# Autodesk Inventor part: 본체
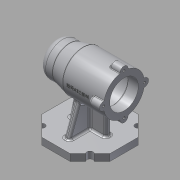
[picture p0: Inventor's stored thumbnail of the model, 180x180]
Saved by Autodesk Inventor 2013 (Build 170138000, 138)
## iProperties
Created: 2021-01
Part Number: 본체
Material: 알루미늄 6061
Document SubType Name: Modeling
Designer: Administrator
Density: 2.71 g/cm^3
Mass: 632.153 g
Surface Area: 615.426 cm^2
Volume: 233.267 cm^3
Author: Administrator
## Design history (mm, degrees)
sketch "스케치1"
  geometry: L1 (0, 0)-(100, 0); L2 (100, 30)-(40, 30); L3 (40, 30)-(20, 25); L4 (20, 25)-(0, 25); L5 (0, 25)-(0, 0); L6 (100, 30)-(100, 21); L7 (100, 21)-(85, 21); L8 (85, 21)-(85, 24); L9 (85, 24)-(43, 24); L10 (43, 24)-(43, 21); L11 (43, 21)-(31, 21); L12 (31, 21)-(31, 17.5); L13 (31, 17.5)-(13, 17.5); L14 (13, 17.5)-(13, 16); L15 (13, 16)-(9, 16); L16 (9, 16)-(9, 10.5); L17 (9, 10.5)-(6, 10.5); L18 (6, 10.5)-(6, 0); 1 further point
  constraints: 36 end point, 12 parallel, 3 perpendicular, 1 coincident, 1 collinear, 1 horizontal, 1 point on line, 1 vertical alignment
  dimensions: "d0" = 100 distance of L1.start L1.end; "d2" = 60 diameter of L2 L1; "d3" = 50 diameter of L4 L1; "d4" = 40 distance from line of L2.end L5; "d5" = 20 distance of L4.end L3.end; "d6" = 42 diameter of L7 L1; "d7" = 48 diameter of L9 L1; "d8" = 42 diameter of L11 L1; "d9" = 35 diameter of L13 L1; "d10" = 32 diameter of L15 L1; "d11" = 21 diameter of L17 L1; "d12" = 15 distance of L6.end L7.end; "d13" = 42 distance of L8.end L9.end; "d14" = 12 distance of L10.end L11.end; "d15" = 18 distance of L12.end L13.end; "d16" = 4 distance of L14.end L15.end; "d17" = 3 distance of L16.end L17.end
revolve "회전1" sketch "스케치1" stored, may be unused: angle "d18" = 90 deg
node "작업 평면1"
sketch "스케치2"
  geometry: L1 (100, -30)-(100, 30) reference; L2 (100, 20.711)-(100, -20.711); L3 (70.711, -50)-(29.289, -50); L4 (0, -20.711)-(0, 20.711); L5 (29.289, 50)-(70.711, 50); L6 (50, 50)-(50, -50); L7 (0, 0)-(100, 0); L8 (70.711, -50)-(100, -20.711); L9 (29.289, -50)-(0, -20.711); L10 (0, 20.711)-(29.289, 50); L11 (70.711, 50)-(100, 20.711); C1 r 50 at (50, 0)
  constraints: 20 end point, 5 perpendicular, 4 midpoint, 4 tangent, 2 point on line, 1 centre point, 1 parallel
  dimensions: "d20" = 50 distance between parallel lines of L6 L2; "d22" = 50 distance between parallel lines of L4 L6; "d24" = 50 distance between parallel lines of L5 L7; "d25" = 50 distance between parallel lines of L3 L7; "d26" = 100 diameter of C1
extrude "돌출1" join sketch "스케치2" distance "d27" = 10; taper "d28" = 0 deg
node "작업 평면2"
node "작업 평면3"
sketch "스케치5"
  geometry: L1 (0, 0)-(-30, 0); A1 r 6 centre (-30, 0) between (-29.4, 5.97) and (-29.4, -5.97); A2 r 30 centre (0, 0) between (-30, 0) and (-29.4, 5.97) reference
  constraints: 5 point on circle, 2 end point, 1 centre point, 1 coincident, 1 horizontal
  dimensions: "d49" = 12 diameter of A1
extrude "돌출3" join sketch "스케치5" distance "d51" = 16; taper "d52" = 0 deg
sketch "스케치6"
  geometry: L1 (29.289, -50)-(70.711, -50) reference; L2 (0, -20.711)-(29.289, -50) reference; L3 (0, 20.711)-(0, -20.711) reference; L4 (29.289, 50)-(0, 20.711) reference; L5 (70.711, 50)-(29.289, 50) reference; L6 (100, 20.711)-(70.711, 50) reference; L7 (100, -20.711)-(100, 20.711) reference; L8 (70.711, -50)-(100, -20.711) reference; L9 (0, -20.711)-(29.289, -50) reference; L10 (70.711, -50)-(100, -20.711) reference; L11 (100, 20.711)-(70.711, 50) reference; L12 (29.289, 50)-(0, 20.711) reference; C1 r 4.5 at (14.645, -35.355); C2 r 4.5 at (85.355, -35.355); C3 r 4.5 at (85.355, 35.355); C4 r 4.5 at (14.645, 35.355); 1 further point
  constraints: 4 centre point, 4 midpoint, 3 equal radius
  dimensions: "d56" = 9 diameter of C4
extrude "돌출4" cut sketch "스케치6" stored distance "d58" = 16; taper "d59" = 0 deg
sketch "스케치7"
  geometry: C1 r 21 at (30, 0) reference; A1 r 30 centre (30, 0) between (0.6, -5.97) and (24.03, -29.4) reference; A2 r 6 centre (30, -30) between (24.03, -29.4) and (35.97, -29.4) reference; A3 r 30 centre (30, 0) between (35.97, -29.4) and (59.4, -5.97) reference; A4 r 6 centre (60, 0) between (59.4, -5.97) and (59.4, 5.97) reference; A5 r 30 centre (30, 0) between (59.4, 5.97) and (35.97, 29.4) reference; A6 r 6 centre (30, 30) between (35.97, 29.4) and (24.03, 29.4) reference; A7 r 30 centre (30, 0) between (24.03, 29.4) and (0.6, 5.97) reference; A8 r 6 centre (0, 0) between (0.6, 5.97) and (0.6, -5.97) reference; 2 further points
  constraints: 1 coincident
hole "구멍1" sketch "스케치7" at (0, 0) diameter "d60" = 3.242; stored, may be unused: countersink angle "d64" = 90 deg, drill point angle "d66" = 118 deg; dims "d61" = 8, "d62" = 4, "d63" = 2, "d65" = 10
sketch "스케치8"
  geometry: L1 (52.884, 10)-(41.421, 10) reference; L2 (47.711, 10)-(47.711, 47); L3 (70.711, 0)-(70.711, 10) reference; L4 (41.421, 10)-(0, 10) reference; L5 (20.711, 10)-(20.711, 47); L6 (20.711, 47)-(47.711, 47); 1 further point
  constraints: 6 end point, 1 midpoint, 1 parallel, 1 perpendicular, 1 point on line, 1 vertical
  dimensions: "d71" = 23 distance from line of L3 L2.start; "d72" = 37 distance of L2.start L2.end
extrude "돌출5" join sketch "스케치8" stored distance "d73" = 8; taper "d74" = 0 deg
sketch "스케치9"
  geometry: L1 (0.987, 47.431)-(-6.289, 10); L2 (-29.289, 0)-(-29.289, 10) reference; L3 (0, 10)-(-11.463, 10) reference; L4 (20.711, 10)-(20.711, 45.268) reference; L5 (10.711, 45)-(54.711, 45) reference; L6 (41.421, 10)-(0, 10) reference; L7 (-9.289, 50)-(10.711, 45) reference; 1 further point
  constraints: 2 end point, 2 point on line
  dimensions: "d76" = 23 distance from line of L2 L1.end; "d77" = 101 deg angle of L3 L1
feature "리브2" sketch "스케치9" dims "d78" = 4, "d79" = 8, "d80" = 0, "d81" = 0, "d82" = 1, "d83" = 1
sketch "스케치10"
  geometry: L1 (-52.293, 1.104)-(-10, -14.289); L2 (0, -29.289)-(-10, -29.289) reference; L3 (-10, -17.827)-(-10, -10.145) reference; L4 (-10, 16.711)-(-47.709, 16.711) reference; L5 (-10, 41.421)-(-10, 0) reference; L6 (-10, 0)-(-10, -11.463) reference; A1 r 30 centre (-75, 20.711) between (-45.268, 24.711) and (-45.268, 16.711) reference; 1 further point
  constraints: 2 end point, 1 point on circle, 1 point on line
  dimensions: "d85" = 15 distance from line of L2 L1.end; "d86" = 110 deg angle of L3 L1
feature "리브3" sketch "스케치10" dims "d87" = 4, "d88" = 8, "d89" = 0, "d90" = 0, "d91" = 1, "d92" = 1
fillet "모깎기2" dims "d93" = 3
fillet "모깎기3" dims "d94" = 3
fillet "모깎기4" dims "d95" = 3
fillet "모깎기5" dims "d96" = 3
fillet "모깎기6" dims "d97" = 1
fillet "모깎기7" dims "d98" = 10
fillet "모깎기8" dims "d99" = 3
fillet "모깎기9" dims "d100" = 0.3
fillet "모깎기10" dims "d101" = 3
node "작업 평면4"
sketch "스케치11"
  geometry: L1 (100, 30.171)-(100, 36) reference; 2 further points
  constraints: 1 horizontal alignment, 1 other
  dimensions: "d103" = 38 distance from line of L1 point (62, 0)
feature "엠보싱1" sketch "스케치11" dims "d104" = 0.5, "d105" = 0
node "솔리드1"
pattern_circular "원형 패턴1" dims angle "d54" = 360 deg
pattern_circular "원형 패턴2" dims angle "d68" = 360 deg
mirror "대칭2"
node "투영된 루프1"
node "투영된 루프2"
other parameters: "d19" = -75, "d102" = -59.25
